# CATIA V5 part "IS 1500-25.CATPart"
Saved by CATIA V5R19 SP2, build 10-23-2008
Part number: IS 1500-25
Bounding box of the stored display mesh (mm): x -37.351 to 37.351, y -37.351 to 37.351, z 0 to 160
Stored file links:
  C:\Users\Bora\Desktop\3D Katı model\IS serisi\IS 1500\IS 1500-25.CATPart
  C:\Program Files\Dassault Systemes\B19\intel_a\reffiles\standard\MetricThickPitch.txt
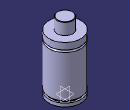
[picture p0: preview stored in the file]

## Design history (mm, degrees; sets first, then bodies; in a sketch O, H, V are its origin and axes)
Body1 (main body)
  Sketch1 on yz-plane, origin (0, 0, 0), H (0, 1, 0), V (0, 0, 1)
    point P1 (37.5, 116.5)
    point P2 (37.5, 132)
    point P4 (37.5, 111.5)
    point P7 (18, 159)
    point P9 (18, 159)
    point P12 (37.5, 116.5)
    point P13 (37.5, 111.5)
    line L1 (37.5, 116.5) -> (37.5, 132)
    line L2 (37.5, 13) -> (37.5, 111.5)
    line L3 (33.5, 13) -> (33.5, 8)
    arc A1 centre (17, 159) radius 1 from (18, 159) to (17, 160) ccw
    line L4 (18, 159) -> (18, 132)
    arc A2 centre (37.5, 114) radius 2.5 from (37.5, 116.5) to (37.5, 111.5) ccw
    point P15 (37.5, 132)
    line L5 (17, 160) -> (0, 160)
    line L6 (18, 132) -> (37.5, 132)
    line L7 (33.5, 8) -> (37.5, 8)
    line L8 (33.5, 13) -> (37.5, 13)
    line L9 (37.5, 8) -> (37.5, 0)
    point P16 (37.5, 0)
    line L10 (0, 0) -> (37.5, 0)
    tangency: L5 A1
    horizontal: L6 H, L7 H, L8 H, L10 H
    coincidence: P16 H, P1 P12, P2 P15, P4 P13, P7 P9
    vertical: L9 V
  Shaft1: profile Sketch1, axis Sketch1.V, angle 360
  Sketch2 on face of Shaft1 from Sketch1.L10, origin (0, 0, 0), H (1, 0, 0), V (0, -1, 0)
    point P1 (20, 0)
    distance P1 V = 20
  Hole1: placed by Sketch2, at (20, 0, 0) direction (0, 0, 1), diameter 6.647, depth 13, threaded "M8", thread diameter 8, thread depth 13, pitch 1.25
  CircPattern1: of Hole1, instances 4, angular step 90, axis from xy-plane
